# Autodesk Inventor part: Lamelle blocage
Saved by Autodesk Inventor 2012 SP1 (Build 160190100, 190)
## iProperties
Created: 2014-12
Part Number: Lamelle blocage
Material: Default
Document SubType Name: Modeling
Designer: Bruno
Density: 1 g/cm^3
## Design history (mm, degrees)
node "Lamelle blocage1"
node "Lamelle blocage"
node "Base1"
